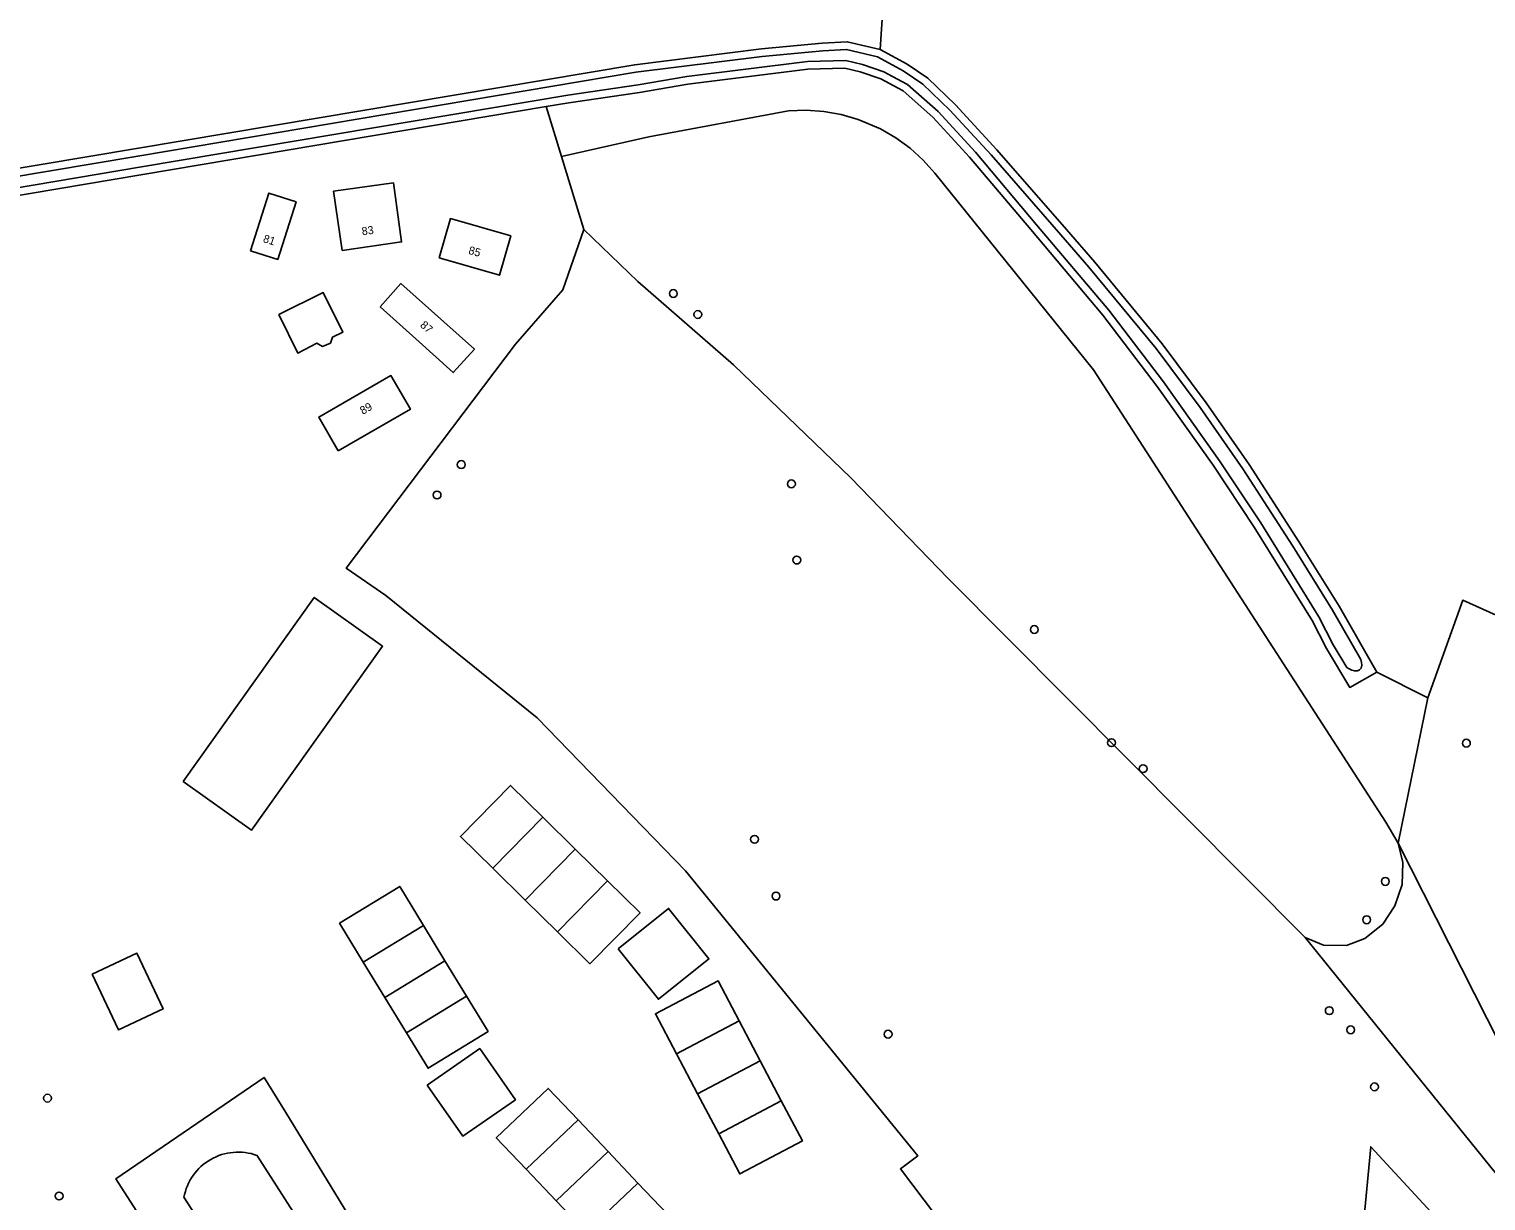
# Model space of a CAD drawing. Extents: x 159451 to 160663, y 388402 to 389723.
# Drawn here: x 159623.4 to 159805.4, y 389378.7 to 389525.1 of the extents above; entities that cross this region are included whole.
import ezdxf

# ---------------------------------------------------------------- set-up
doc = ezdxf.new("R2010")
doc.units = 0
for name, color, linetype in [('IMGEO_Boom', 7, 'Continuous'), ('IMGEO_Greppel_droge_sloot', 7, 'Continuous'), ('IMGEO_Groenvoorziening', 7, 'Continuous'), ('IMGEO_Loofbos', 7, 'Continuous'), ('IMGEO_Pand', 7, 'Continuous'), ('IMGEO_Pand_nummerreeks', 7, 'Continuous'), ('IMGEO_Pand_vergunning_verleend', 7, 'Continuous'), ('IMGEO_Rijbaan_lokaal_gesloten', 7, 'Continuous')]:
    doc.layers.add(name, color=color, linetype=linetype)

msp = doc.modelspace()

# ---------------------------------------------------------------- linework, layer by layer
at = {"layer": 'IMGEO_Boom'}
for centre in [(159703.89, 389492.02), (159706.95, 389489.4), (159677.39, 389470.65), (159718.65, 389468.24), (159674.37, 389466.85), (159719.32, 389458.72), (159749.01, 389450.04), (159758.65, 389435.9), (159803, 389435.84), (159762.6, 389432.66), (159714.04, 389423.83), (159792.86, 389418.57), (159716.73, 389416.74), (159790.53, 389413.78), (159785.86, 389402.42), (159730.73, 389399.48), (159788.54, 389400.03), (159625.69, 389391.49), (159791.51, 389392.9), (159627.14, 389379.27)]:
    msp.add_circle(centre, 0.489, dxfattribs=at)
at = {"layer": 'IMGEO_Greppel_droge_sloot'}
for points in [[(159788.06, 389445.28), (159788.36, 389445.12), (159788.69, 389444.97), (159789, 389444.87), (159789.39, 389444.87), (159789.65, 389445.01), (159789.84, 389445.23), (159789.93, 389445.59), (159789.9, 389445.94), (159789.82, 389446.3), (159786.26, 389452.47), (159781.32, 389460.44), (159775.05, 389470.11), (159769.72, 389477.79), (159764.23, 389485.16), (159755.83, 389495.32), (159752.3, 389499.37), (159743.62, 389509.35), (159738.45, 389514.92), (159735.08, 389518.19), (159732.63, 389519.84), (159729.4, 389521.61), (159725.54, 389522.51), (159722.58, 389522.36), (159715, 389521.63), (159699.21, 389519.66), (159636.97, 389509.2), (159576.64, 389499.06)], [(159596.51, 389500.94), (159637.44, 389507.84), (159690.69, 389516.8), (159699.51, 389518.1), (159705.57, 389519.14), (159720.65, 389521), (159725.44, 389521.13), (159727.53, 389520.63), (159730.19, 389519.71), (159732.43, 389518.52), (159733.15, 389518.14), (159737, 389514.75), (159741.64, 389509.7), (159749.29, 389500.62), (159758.3, 389489.93), (159765.13, 389480.99), (159772.16, 389471.12), (159777.29, 389463.37), (159784.54, 389451.63), (159786.35, 389448.14), (159788.06, 389445.28)]]:
    msp.add_lwpolyline(points, dxfattribs=at)
at = {"layer": 'IMGEO_Groenvoorziening'}
for points in [[(159791.82, 389444.73), (159787.08, 389452.96), (159782.12, 389460.95), (159775.85, 389470.64), (159770.49, 389478.35), (159764.98, 389485.75), (159756.56, 389495.94), (159753.02, 389500), (159744.33, 389509.98), (159739.14, 389515.59), (159735.68, 389518.93), (159733.13, 389520.66), (159729.75, 389522.51)], [(159791.82, 389444.73), (159788.43, 389442.8), (159785.52, 389447.67), (159783.71, 389451.16), (159776.49, 389462.85), (159771.37, 389470.58), (159764.36, 389480.42), (159757.55, 389489.33), (159748.56, 389500), (159740.92, 389509.07), (159736.33, 389514.06), (159732.6, 389517.34), (159731.98, 389517.67), (159729.81, 389518.83), (159727.26, 389519.71), (159725.34, 389520.17), (159720.72, 389520.04), (159705.71, 389518.19), (159699.66, 389517.15), (159690.84, 389515.86), (159688.02, 389515.39)], [(159688.02, 389515.39), (159637.6, 389506.89), (159598.51, 389500.31)], [(159689.92, 389509.16), (159688.02, 389515.39)], [(159813.75, 389448.69), (159802.55, 389453.69), (159798.18, 389441.51)], [(159798.18, 389441.51), (159791.82, 389444.73)], [(159794.48, 389423.34), (159798.18, 389441.51)]]:
    msp.add_lwpolyline(points, dxfattribs=at)
at = {"layer": 'IMGEO_Loofbos'}
for points in [[(159729.75, 389522.51), (159731.83, 389554.33)], [(159488.62, 389330.56), (159500, 389426.96), (159502.71, 389450.67), (159503.58, 389456.3), (159504.7, 389461.53), (159506.19, 389466.88), (159508.08, 389471.72), (159511.76, 389477.05), (159516.65, 389481.48), (159520.54, 389484.36), (159524.32, 389486.57), (159529.53, 389488.52), (159536.95, 389490.76), (159549.25, 389493.78), (159576.46, 389500), (159636.81, 389510.14), (159699.07, 389520.6), (159714.9, 389522.58), (159722.51, 389523.32), (159725.62, 389523.47), (159729.75, 389522.51)], [(159689.92, 389509.16), (159700.83, 389511.58), (159718.3, 389514.83), (159720.5, 389514.91), (159722.7, 389514.76), (159724.87, 389514.38), (159726.99, 389513.78), (159729.79, 389512.59), (159731.69, 389511.48), (159733.47, 389510.18), (159735.11, 389508.7), (159736.57, 389507.05), (159756.38, 389482.5), (159792.91, 389425.98), (159794.48, 389423.34)], [(159692.72, 389500), (159689.92, 389509.16)], [(159871.96, 389278.31), (159856.3, 389302.19), (159835.93, 389332.46), (159821.1, 389351.87), (159816.71, 389357.62), (159791.04, 389385.41), (159788.61, 389359.57), (159782.92, 389353.41), (159786.17, 389346.9), (159774.32, 389338.96), (159772.15, 389341.51), (159744.65, 389323.51), (159741.65, 389327.63), (159762.21, 389343.03), (159732.27, 389382.65), (159734.43, 389384.27), (159705.43, 389419.91), (159686.88, 389439.01), (159667.95, 389454.31), (159663.03, 389457.69), (159684.18, 389485.7), (159690.1, 389492.47), (159692.72, 389500)], [(159782.84, 389411.56), (159738.22, 389456.43), (159726.07, 389468.98), (159711.41, 389483.1), (159699.45, 389493.54), (159692.72, 389500)], [(159794.48, 389423.34), (159795.07, 389420.92), (159794.97, 389418.19), (159794.05, 389415.51), (159792.55, 389413.25), (159790.3, 389411.43), (159788, 389410.57), (159785.15, 389410.62), (159782.84, 389411.56)], [(159881.39, 389288.32), (159874.34, 389299.54), (159850.68, 389337.23), (159831.1, 389366.95), (159811.91, 389388.9), (159794.48, 389423.34)], [(159782.84, 389411.56), (159827.32, 389356.54), (159838.14, 389339.9), (159876.34, 389281.17)]]:
    msp.add_lwpolyline(points, dxfattribs=at)
at = {"layer": 'IMGEO_Pand'}
for points in [[(159662.49, 389497.41), (159661.43, 389504.79), (159668.91, 389505.84), (159669.93, 389498.47), (159662.49, 389497.41)], [(159651.07, 389497.37), (159653.36, 389504.57), (159656.75, 389503.46), (159654.46, 389496.28), (159651.07, 389497.37)], [(159674.62, 389496.47), (159676.03, 389501.38), (159683.58, 389499.21), (159682.17, 389494.31), (159674.62, 389496.47)], [(159667.25, 389490.37), (159669.85, 389493.27), (159679.04, 389485.08), (159676.39, 389482.14), (159671.73, 389486.34), (159667.25, 389490.37)], [(159662.01, 389472.37), (159659.59, 389476.58), (159668.61, 389481.77), (159671.03, 389477.56), (159662.01, 389472.37)]]:
    msp.add_lwpolyline(points, dxfattribs=at)
at = {"layer": 'IMGEO_Pand_vergunning_verleend'}
for points in [[(159654.6, 389489.4), (159660.15, 389492.13), (159662.58, 389487.19), (159661.31, 389486.57), (159661.04, 389485.83), (159660.05, 389485.41), (159659.33, 389485.81), (159656.96, 389484.58), (159654.6, 389489.4)], [(159642.63, 389431.05), (159659.02, 389454.05), (159667.55, 389447.96), (159651.16, 389424.96), (159642.63, 389431.05)], [(159681.33, 389420.22), (159677.28, 389424.2), (159683.55, 389430.57), (159687.59, 389426.59)], [(159681.33, 389420.22), (159687.59, 389426.59)], [(159687.59, 389426.59), (159691.64, 389422.61)], [(159691.64, 389422.61), (159685.37, 389416.24)], [(159691.64, 389422.61), (159695.68, 389418.63)], [(159685.37, 389416.24), (159681.33, 389420.22)], [(159665.15, 389408.49), (159662.18, 389413.35), (159669.7, 389417.94), (159672.66, 389413.08)], [(159695.68, 389418.63), (159689.42, 389412.26)], [(159695.68, 389418.63), (159699.73, 389414.65), (159693.46, 389408.28), (159689.42, 389412.26)], [(159689.42, 389412.26), (159685.37, 389416.24)], [(159696.99, 389410.15), (159703.29, 389415.19), (159708.33, 389408.89), (159702.03, 389403.85), (159696.99, 389410.15)], [(159665.15, 389408.49), (159672.66, 389413.08)], [(159672.66, 389413.08), (159675.36, 389408.66)], [(159631.28, 389406.97), (159636.86, 389409.6), (159640.14, 389402.64), (159634.56, 389400.01), (159631.28, 389406.97)], [(159667.84, 389404.07), (159665.15, 389408.49)], [(159667.84, 389404.07), (159675.36, 389408.66)], [(159675.36, 389408.66), (159678.06, 389404.24)], [(159704.3, 389397.04), (159701.66, 389402.04), (159709.48, 389406.16), (159712.11, 389401.16)], [(159670.54, 389399.65), (159667.84, 389404.07)], [(159670.54, 389399.65), (159678.06, 389404.24)], [(159678.06, 389404.24), (159680.75, 389399.82), (159673.24, 389395.23), (159670.54, 389399.65)], [(159712.11, 389401.16), (159704.3, 389397.04)], [(159712.11, 389401.16), (159714.75, 389396.15)], [(159673.14, 389393.12), (159679.71, 389397.69), (159684.15, 389391.3), (159677.59, 389386.73), (159673.14, 389393.12)], [(159706.93, 389392.04), (159704.3, 389397.04)], [(159714.75, 389396.15), (159706.93, 389392.04)], [(159714.75, 389396.15), (159717.38, 389391.15)], [(159685.51, 389382.61), (159681.77, 389386.55), (159688.25, 389392.7), (159691.99, 389388.77)], [(159709.57, 389387.03), (159706.93, 389392.04)], [(159717.38, 389391.15), (159709.57, 389387.03)], [(159717.38, 389391.15), (159720.02, 389386.15), (159712.2, 389382.03), (159709.57, 389387.03)], [(159685.51, 389382.61), (159691.99, 389388.77)], [(159691.99, 389388.77), (159695.73, 389384.83)], [(159689.25, 389378.67), (159695.73, 389384.83)], [(159695.73, 389384.83), (159699.47, 389380.89)], [(159689.25, 389378.67), (159685.51, 389382.61)], [(159693, 389374.74), (159699.47, 389380.89)], [(159699.47, 389380.89), (159703.21, 389376.96), (159696.74, 389370.8), (159693, 389374.74)], [(159693, 389374.74), (159689.25, 389378.67)]]:
    msp.add_lwpolyline(points, dxfattribs=at)
at = {"layer": 'IMGEO_Rijbaan_lokaal_gesloten'}
for points in [[(159656.13, 389347.78), (159637.53, 389376.31), (159634.21, 389381.4), (159652.75, 389394.08), (159655.46, 389389.69), (159680.67, 389348.37), (159655.34, 389331.64), (159623.74, 389311.39)], [(159670.77, 389354.89), (159651.84, 389384.35)], [(159642.74, 389379.11), (159662.42, 389348.77)]]:
    msp.add_lwpolyline(points, dxfattribs=at)
msp.add_arc((159649.52, 389377.85), 6.9, 70.344, 169.5205, dxfattribs=at)

# ---------------------------------------------------------------- texts
at = {"layer": 'IMGEO_Pand_nummerreeks'}
for s, rotation, p in [('81', 342.1581, (159652.55, 389498.47)), ('83', 8.0558, (159665.03, 389499.29)), ('85', 344.0259, (159678.22, 389497)), ('87', 318.0194, (159672.17, 389487.96)), ('89', 29.9199, (159665.09, 389476.86))]:
    msp.add_text(s, height=1, rotation=rotation, dxfattribs=at).set_placement(p)

doc.saveas('drawing.dxf')
